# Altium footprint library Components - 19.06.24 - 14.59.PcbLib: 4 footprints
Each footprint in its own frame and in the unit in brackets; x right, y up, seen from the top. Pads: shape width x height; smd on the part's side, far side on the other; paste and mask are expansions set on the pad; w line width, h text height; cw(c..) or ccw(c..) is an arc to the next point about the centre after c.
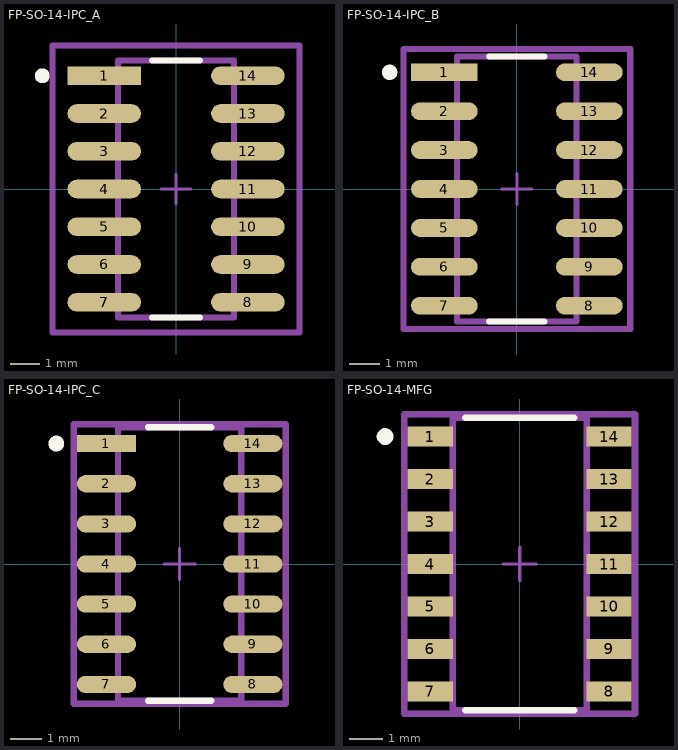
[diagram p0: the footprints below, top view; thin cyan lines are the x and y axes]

## FP-SO-14-IPC_A [mil]
pads (14):
  rect 97.4x24.54 smd paste+0 mask+0: 1(-95.12,150)
  rrect100% 97.4x24.54 smd paste+0 mask+0: 2(-95.12,100) 3(-95.12,50) 4(-95.12,0) 5(-95.12,-50) 6(-95.12,-100) 7(-95.12,-150) 8(95.12,-150) 9(95.12,-100) 10(95.12,-50) 11(95.12,0) 12(95.12,50) 13(95.12,100) 14(95.12,150)
Top Overlay:
  circle w9.84: c-177.29,150 r4.92
  lines w7.87: -31.65,-170.28 31.65,-170.28 ; -31.65,170.28 31.65,170.28
Top Assembly:
  lines w7.87: -163.51,-189.96 163.51,-189.96 163.51,189.96 -163.51,189.96 -163.51,-189.96
  text ".Designator" at 0,7.38 h39.37
Top 3D Body:
  lines w7.87: -76.77,-170.28 76.77,-170.28 76.77,170.28 -76.77,170.28 -76.77,-170.28
Top Courtyard:
  lines w7.87: -163.51,-189.96 163.51,-189.96 163.51,189.96 -163.51,189.96 -163.51,-189.96
Top Component Center:
  lines w3.94: -19.68,0 19.68,0 ; 0,-19.68 0,19.68
3D body "IC_STMicroelectronics_LM324DT_eec.STEP": height 10, standoff 0, extent -163.51,-189.96 163.51,189.96

## FP-SO-14-IPC_B [mil]
pads (14):
  rect 85.59x22.97 smd paste+0 mask+0: 1(-93.15,150)
  rrect100% 85.59x22.97 smd paste+0 mask+0: 2(-93.15,100) 3(-93.15,50) 4(-93.15,0) 5(-93.15,-50) 6(-93.15,-100) 7(-93.15,-150) 8(93.15,-150) 9(93.15,-100) 10(93.15,-50) 11(93.15,0) 12(93.15,50) 13(93.15,100) 14(93.15,150)
Top Overlay:
  circle w9.84: c-163.51,150 r4.92
  lines w7.87: -35.59,-170.28 35.59,-170.28 ; -35.59,170.28 35.59,170.28
Top Assembly:
  lines w7.87: -145.79,-180.12 145.79,-180.12 145.79,180.12 -145.79,180.12 -145.79,-180.12
  text ".Designator" at 0,7.38 h39.37
Top 3D Body:
  lines w7.87: -76.77,-170.28 76.77,-170.28 76.77,170.28 -76.77,170.28 -76.77,-170.28
Top Courtyard:
  lines w7.87: -145.79,-180.12 145.79,-180.12 145.79,180.12 -145.79,180.12 -145.79,-180.12
Top Component Center:
  lines w3.94: -19.68,0 19.68,0 ; 0,-19.68 0,19.68
3D body "IC_STMicroelectronics_LM324DT_eec.STEP": height 10, standoff 0, extent -145.79,-180.12 145.79,180.12

## FP-SO-14-IPC_C [mil]
pads (14):
  rect 73.78x21.39 smd paste+0 mask+0: 1(-91.18,150)
  rrect100% 73.78x21.39 smd paste+0 mask+0: 2(-91.18,100) 3(-91.18,50) 4(-91.18,0) 5(-91.18,-50) 6(-91.18,-100) 7(-91.18,-150) 8(91.18,-150) 9(91.18,-100) 10(91.18,-50) 11(91.18,0) 12(91.18,50) 13(91.18,100) 14(91.18,150)
Top Overlay:
  circle w9.84: c-153.67,150 r4.92
  lines w7.87: -39.53,-170.28 39.53,-170.28 ; -39.53,170.28 39.53,170.28
Top Assembly:
  lines w7.87: -132.01,-174.21 132.01,-174.21 132.01,174.21 -132.01,174.21 -132.01,-174.21
  text ".Designator" at 0,7.38 h39.37
Top 3D Body:
  lines w7.87: -76.77,-170.28 76.77,-170.28 76.77,170.28 -76.77,170.28 -76.77,-170.28
Top Courtyard:
  lines w7.87: -132.01,-174.21 132.01,-174.21 132.01,174.21 -132.01,174.21 -132.01,-174.21
Top Component Center:
  lines w3.94: -19.68,0 19.68,0 ; 0,-19.68 0,19.68
3D body "IC_STMicroelectronics_LM324DT_eec.STEP": height 10, standoff 0, extent -132.01,-174.21 132.01,174.21

## FP-SO-14-MFG [mm]
pads (14):
  rect 1.35x0.6 smd paste+0 mask+0: 1(-2.675,3.81) 2(-2.675,2.54) 3(-2.675,1.27) 4(-2.675,0) 5(-2.675,-1.27) 6(-2.675,-2.54) 7(-2.675,-3.81) 8(2.675,-3.81) 9(2.675,-2.54) 10(2.675,-1.27) 11(2.675,0) 12(2.675,1.27) 13(2.675,2.54) 14(2.675,3.81)
Top Overlay:
  circle w0.25: c-4.025,3.81 r0.125
  lines w0.2: -1.625,-4.375 1.625,-4.375 ; -1.625,4.375 1.625,4.375
Top Assembly:
  lines w0.2: -3.45,-4.475 3.45,-4.475 3.45,4.475 -3.45,4.475 -3.45,-4.475
  text ".Designator" at 0,0.187 h1
Top 3D Body:
  lines w0.2: -2,-4.375 2,-4.375 2,4.375 -2,4.375 -2,-4.375
Top Courtyard:
  lines w0.2: -3.45,-4.475 3.45,-4.475 3.45,4.475 -3.45,4.475 -3.45,-4.475
Top Component Center:
  lines w0.1: -0.5,0 0.5,0 ; 0,-0.5 0,0.5
3D body "IC_STMicroelectronics_LM324DT_eec.STEP": height 0.25, standoff 0, extent -3.45,-4.475 3.45,4.475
